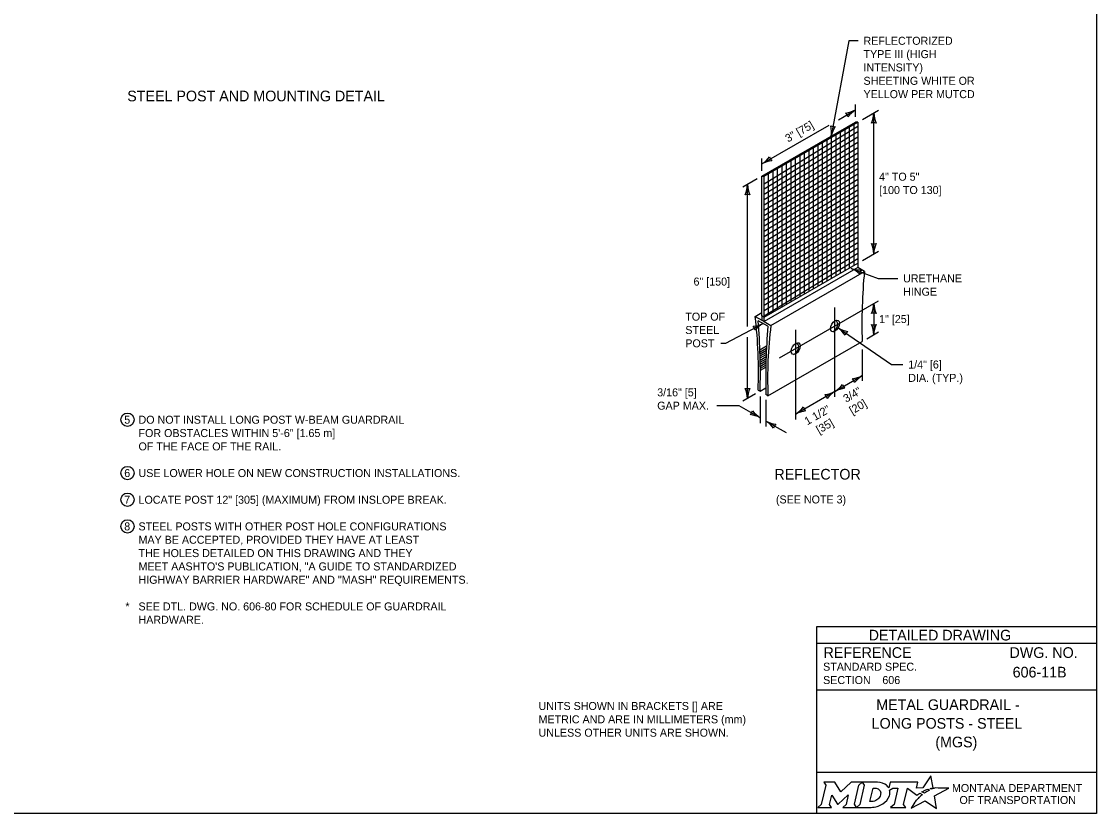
# Model space of a CAD drawing. Extents: x 49991.4 to 50021, y 49987.6 to 50011.4.
# Drawn here: x 50008.69 to 50016.75, y 49987.8 to 49993.74 of the extents above; entities that cross this region are included whole.
import ezdxf

# ---------------------------------------------------------------- set-up
doc = ezdxf.new("R2010")
doc.units = 0
for name, color, linetype in [('Default', 7, 'Continuous'), ('Level 1', 7, 'Continuous'), ('Level 2', 7, 'Continuous'), ('Level 3', 7, 'Continuous'), ('Level 5', 7, 'Continuous')]:
    doc.layers.add(name, color=color, linetype=linetype)

msp = doc.modelspace()

# ---------------------------------------------------------------- linework, layer by layer
at = {"layer": 'Default'}
for points in [[(50015.5126, 49987.9811), (50015.5023, 49987.9867), (50015.5139, 49987.9895), (50015.5255, 49987.9915), (50015.5081, 49988.0816), (50015.4486, 49987.9903), (50015.4013, 49987.9896), (50015.4116, 49988.0337), (50015.2024, 49988.0338), (50015.1923, 49987.9913), (50015.1865, 49987.9996)], [(50014.7056, 49988.0338), (50014.7197, 49988.0104), (50014.6862, 49987.8671), (50014.6605, 49987.8446), (50014.7621, 49987.8446), (50014.7486, 49987.8674), (50014.7648, 49987.9375), (50014.8085, 49987.8685), (50014.8138, 49987.8685), (50014.8889, 49987.938), (50014.8725, 49987.8669), (50014.8478, 49987.8449), (50014.9494, 49987.8449), (50014.9356, 49987.8682), (50014.9688, 49988.0106)], [(50014.9688, 49988.0106), (50014.9941, 49988.0338), (50014.9117, 49988.0338), (50014.8321, 49987.9608), (50014.7876, 49988.0335), (50014.7056, 49988.0338)], [(50015.1077, 49988.0338), (50014.9941, 49988.0338), (50015.0088, 49988.0109), (50014.9749, 49987.8671), (50014.9494, 49987.8449), (50015.06, 49987.8449)], [(50015.1317, 49987.9471), (50015.1305, 49987.939), (50015.1273, 49987.9297), (50015.1231, 49987.9215), (50015.1175, 49987.914), (50015.111, 49987.9071), (50015.1031, 49987.9008), (50015.0948, 49987.8961), (50015.0857, 49987.8922), (50015.0766, 49987.8899), (50015.0674, 49987.889), (50015.0515, 49987.889), (50015.0751, 49987.989), (50015.0911, 49987.989), (50015.0987, 49987.9884), (50015.1063, 49987.9865), (50015.1129, 49987.9835), (50015.119, 49987.9793), (50015.1238, 49987.9743), (50015.1275, 49987.9683), (50015.1302, 49987.9621), (50015.1318, 49987.9547), (50015.1318, 49987.9517), (50015.1317, 49987.9471)], [(50015.1991, 49987.9747), (50015.2237, 49987.9878), (50015.2606, 49987.9878), (50015.232, 49987.8673), (50015.2045, 49987.8446), (50015.3207, 49987.8446), (50015.3037, 49987.8675), (50015.3319, 49987.9877), (50015.4032, 49987.936), (50015.4243, 49987.9511), (50015.444, 49987.9402)], [(50015.3882, 49987.8843), (50015.3729, 49987.8599), (50015.3682, 49987.8524), (50015.3624, 49987.8438), (50015.3601, 49987.8395), (50015.4654, 49987.8926), (50015.5493, 49987.8375), (50015.5362, 49987.9302), (50015.6431, 49987.9886), (50015.5938, 49987.9894), (50015.5637, 49987.9898), (50015.5429, 49987.9901), (50015.5361, 49987.9886), (50015.5312, 49987.9874), (50015.5228, 49987.9851), (50015.5126, 49987.9811)], [(50015.4622, 49987.9535), (50015.4598, 49987.9518), (50015.4415, 49987.9614), (50015.4518, 49987.9671), (50015.4559, 49987.9693), (50015.4645, 49987.9733), (50015.4702, 49987.9759), (50015.4781, 49987.9789), (50015.4854, 49987.9816), (50015.4972, 49987.9742), (50015.4932, 49987.9721), (50015.4886, 49987.9696), (50015.4844, 49987.9674), (50015.4794, 49987.9645), (50015.4775, 49987.9634), (50015.4748, 49987.9618), (50015.4723, 49987.9604), (50015.47, 49987.9588), (50015.4674, 49987.957), (50015.4647, 49987.9552), (50015.4622, 49987.9535)], [(50015.1057, 49987.8522), (50015.1141, 49987.8548), (50015.1271, 49987.8602), (50015.1475, 49987.8712)], [(50015.4021, 49987.9004), (50015.4021, 49987.9004)]]:
    msp.add_lwpolyline(points, dxfattribs=at)
for centre, radius, start, end in [((50015.0868, 49987.9727), 0.1183, 300.91025, 339.13831), ((50015.1308, 49987.9554), 0.0709, 339.53292, 15.85821)]:
    msp.add_arc(centre, radius, start, end, dxfattribs=at)
for centre, major_axis, ratio, start_param, end_param in [((50015.1056, 49987.9864), (0.0834, -0.0037), 0.568097, 0.61298, 1.570796), ((50015.1612, 49987.9937), (0.0361, -0.0295), 0.469099, 1.225588, 1.570796), ((50015.4119, 49987.9106), (-0.0098, -0.0102), 0.016458, 3.141593, 6.279097), ((50015.4329, 49987.9305), (-0.0112, -0.0097), 0.021651, 3.157348, 6.283185), ((50015.0603, 49987.9932), (0, 0.1484), 0.987302, 3.139398, 3.456847), ((50015.3952, 49987.8923), (-0.00694, -0.00806), 0.008222, 0, 3.137361)]:
    msp.add_ellipse(centre, major_axis=major_axis, ratio=ratio, start_param=start_param, end_param=end_param, dxfattribs=at)
at = {"layer": 'Level 1'}
for p, q in [((50014.2414, 49992.5772), (50014.9429, 49992.9822)), ((50014.2583, 49992.5772), (50014.9598, 49992.9822)), ((50014.2583, 49992.5211), (50014.9598, 49992.9514)), ((50014.8651, 49991.8714), (50014.8651, 49992.9276)), ((50014.8988, 49991.8909), (50014.8988, 49992.9471)), ((50014.9326, 49991.9104), (50014.9326, 49992.9665)), ((50014.9598, 49992.9822), (50014.9429, 49992.9822)), ((50014.9598, 49992.9822), (50014.9598, 49991.9261)), ((50014.2583, 49992.4815), (50014.9598, 49992.9118)), ((50014.2583, 49992.4419), (50014.9598, 49992.8722)), ((50014.7301, 49991.7935), (50014.7301, 49992.8496)), ((50014.7638, 49991.813), (50014.7638, 49992.8691)), ((50014.7976, 49991.8325), (50014.7976, 49992.8886)), ((50014.8313, 49991.852), (50014.8313, 49992.9081)), ((50014.2583, 49992.4023), (50014.9598, 49992.8326)), ((50014.2583, 49992.3627), (50014.9598, 49992.793)), ((50014.2583, 49992.3231), (50014.9598, 49992.7534)), ((50014.5951, 49991.7156), (50014.5951, 49992.7717)), ((50014.6288, 49991.735), (50014.6288, 49992.7912)), ((50014.6626, 49991.7545), (50014.6626, 49992.8107)), ((50014.6963, 49991.774), (50014.6963, 49992.8301)), ((50014.2583, 49992.2836), (50014.9598, 49992.7138)), ((50014.2583, 49992.244), (50014.9598, 49992.6742)), ((50014.4263, 49991.6181), (50014.4263, 49992.6743)), ((50014.4601, 49991.6376), (50014.4601, 49992.6937)), ((50014.4938, 49991.6571), (50014.4938, 49992.7132)), ((50014.5276, 49991.6766), (50014.5276, 49992.7327)), ((50014.5613, 49991.6961), (50014.5613, 49992.7522)), ((50014.2583, 49992.2044), (50014.9598, 49992.6346)), ((50014.2583, 49992.1648), (50014.9598, 49992.595)), ((50014.2913, 49991.5402), (50014.2913, 49992.5963)), ((50014.3251, 49991.5597), (50014.3251, 49992.6158)), ((50014.3588, 49991.5792), (50014.3588, 49992.6353)), ((50014.3926, 49991.5986), (50014.3926, 49992.6548)), ((50014.2414, 49991.5309), (50014.2414, 49992.5772)), ((50014.2414, 49992.5772), (50014.2583, 49992.5772)), ((50014.2583, 49991.5211), (50014.2583, 49992.5772)), ((50014.2583, 49992.1252), (50014.9598, 49992.5554)), ((50014.2583, 49992.0856), (50014.9598, 49992.5158)), ((50014.2583, 49992.046), (50014.9598, 49992.4762)), ((50014.2583, 49992.0064), (50014.9598, 49992.4367)), ((50014.2583, 49991.9668), (50014.9598, 49992.3971)), ((50014.2583, 49991.9272), (50014.9598, 49992.3575)), ((50014.2583, 49991.8876), (50014.9598, 49992.3179)), ((50014.2583, 49991.848), (50014.9598, 49992.2783)), ((50014.2583, 49991.8084), (50014.9598, 49992.2387)), ((50014.2583, 49991.7688), (50014.9598, 49992.1991)), ((50014.2583, 49991.7293), (50014.9598, 49992.1595)), ((50014.2583, 49991.6897), (50014.9598, 49992.1199)), ((50014.2583, 49991.6501), (50014.9598, 49992.0803)), ((50014.2583, 49991.6105), (50014.9598, 49992.0407)), ((50014.2583, 49991.5709), (50014.9598, 49992.0011)), ((50014.2583, 49991.5313), (50014.9598, 49991.9615)), ((50014.2583, 49991.5211), (50014.9598, 49991.9261)), ((50014.9598, 49991.8924), (50014.2583, 49991.4874)), ((50014.9598, 49991.9261), (50014.9598, 49991.8924)), ((50014.9598, 49991.9219), (50014.9598, 49991.9219)), ((50015.0099, 49991.8636), (50014.9598, 49991.8924)), ((50014.3084, 49991.4586), (50015.0099, 49991.8636)), ((50014.1915, 49991.5261), (50014.2414, 49991.5549)), ((50014.1915, 49991.5261), (50014.2414, 49991.4972)), ((50014.2865, 49991.4517), (50014.2134, 49991.4939)), ((50014.2583, 49991.5211), (50014.2414, 49991.5309)), ((50014.2414, 49991.5309), (50014.2414, 49991.4972)), ((50014.2414, 49991.4972), (50014.2583, 49991.4874)), ((50014.2583, 49991.4874), (50014.2583, 49991.5211)), ((50014.2583, 49991.4874), (50014.2583, 49991.5211)), ((50014.2583, 49991.4874), (50014.3084, 49991.4586)), ((50014.2264, 49991.2758), (50014.2762, 49991.3045)), ((50014.2865, 49990.9312), (50014.993, 49991.3391)), ((50014.227, 49991.2605), (50014.2754, 49991.2885)), ((50014.2275, 49991.2452), (50014.2746, 49991.2724)), ((50014.2279, 49991.2299), (50014.2739, 49991.2564)), ((50014.2283, 49991.2145), (50014.2733, 49991.2405)), ((50014.2287, 49991.1991), (50014.2727, 49991.2246)), ((50014.229, 49991.1837), (50014.2722, 49991.2087)), ((50014.2292, 49991.1683), (50014.2717, 49991.1928)), ((50014.2295, 49991.1528), (50014.2713, 49991.177)), ((50014.2296, 49991.1373), (50014.2709, 49991.1612)), ((50014.2297, 49991.1218), (50014.2706, 49991.1454)), ((50014.2281, 49990.965), (50014.2707, 49990.9896)), ((50014.2134, 49990.9734), (50014.2281, 49990.965)), ((50014.2865, 49990.9312), (50014.2719, 49990.9396))]:
    msp.add_line(p, q, dxfattribs=at)
msp.add_lwpolyline([(49999.3835, 49998.9992), (50016.7501, 49998.9992), (50016.7501, 49987.7988), (49999.3835, 49987.7988)], close=True, dxfattribs=at)
for centre, radius, start, end in [((50019.1969, 49991.4663), 4.2058, 174.58065, 181.73332), ((50010.5166, 49991.1035), 3.6991, 357.984, 6.55893), ((50009.3581, 49991.0951), 4.8717, 358.46937, 4.69582), ((50018.6911, 49991.0698), 4.4211, 175.04388, 181.68667), ((50017.51, 49991.0613), 3.2261, 172.92757, 182.31169)]:
    msp.add_arc(centre, radius, start, end, dxfattribs=at)
for centre, major_axis in [((50014.7886, 49991.4549), (0.0239, 0.0413)), ((50014.4947, 49991.2852), (0.024, 0.0415))]:
    msp.add_ellipse(centre, major_axis=major_axis, ratio=0.57735, dxfattribs=at)
for centre, major_axis, start_param, end_param in [((50014.778, 49991.4507), (0.0228, 0.0395), 3.80014, 6.895622), ((50014.487, 49991.2803), (0.0214, 0.0371), 3.593264, 7.511454)]:
    msp.add_ellipse(centre, major_axis=major_axis, ratio=0.57735, start_param=start_param, end_param=end_param, dxfattribs=at)
at = {"layer": 'Level 2'}
for centre in [(50009.4843, 49990.7517), (50009.4843, 49990.3517), (50009.4843, 49990.1517), (50009.4843, 49989.9517)]:
    msp.add_circle(centre, 0.05, dxfattribs=at)
at = {"layer": 'Level 3'}
for p, q in [((50014.894, 49993.5927), (50014.761, 49992.8772)), ((50014.9631, 49993.5927), (50014.894, 49993.5927)), ((50014.9429, 49993.0222), (50014.9429, 49993.1146)), ((50014.8148, 49993.0007), (50014.9429, 49993.0746)), ((50014.9944, 49993.0022), (50015.1147, 49993.0717)), ((50015.0801, 49991.9956), (50015.0801, 49993.0517)), ((50014.2414, 49992.6696), (50014.7456, 49992.9607)), ((50014.2414, 49992.6172), (50014.2414, 49992.7096)), ((50014.2068, 49992.5572), (50014.0988, 49992.4949)), ((50014.1334, 49991.4506), (50014.1334, 49992.5149)), ((50014.9944, 49991.9461), (50015.1147, 49992.0156)), ((50014.91, 49991.8858), (50015.1133, 49991.8113)), ((50015.1133, 49991.8113), (50015.2601, 49991.8113)), ((50015.0801, 49991.6232), (50015.0801, 49991.3894)), ((50013.972, 49991.3243), (50014.25, 49991.4728)), ((50014.8125, 49991.4412), (50015.214, 49991.1654)), ((50015.0277, 49991.3591), (50015.1147, 49991.4094)), ((50013.9331, 49991.3243), (50013.972, 49991.3243)), ((50014.1334, 49990.9103), (50014.1334, 49991.3706)), ((50014.993, 49991.2772), (50014.993, 49991.0419)), ((50015.214, 49991.1654), (50015.2986, 49991.1654)), ((50014.7886, 49990.9639), (50014.993, 49991.0819)), ((50014.1934, 49990.945), (50014.0988, 49990.8903)), ((50014.2281, 49990.925), (50014.2281, 49990.7264)), ((50014.2719, 49990.8996), (50014.2719, 49990.7011)), ((50014.7886, 49990.9639), (50014.4947, 49990.7942)), ((50014.0718, 49990.8566), (50013.9035, 49990.8566)), ((50014.2281, 49990.7664), (50014.0718, 49990.8566)), ((50014.2719, 49990.7411), (50014.4221, 49990.6544))]:
    msp.add_line(p, q, dxfattribs=at)
for centre, radius, start, end in [((50014.8398, 49993.2716), 0.2223, 277.45601, 297.63952), ((50014.8319, 49993.0105), 0.0548, 12.13882, 47.86118), ((50015.0692, 49992.8788), 0.233, 122.82731, 142.07716), ((50014.8579, 49993.0608), 0.2223, 337.45601, 357.63952), ((50015.3128, 49993.0632), 0.233, 182.82731, 202.07716), ((50014.7844, 49993.0033), 0.0548, 241.60423, 277.32659), ((50014.5301, 49992.9084), 0.233, 352.29272, 11.54257), ((50014.9777, 49992.8276), 0.2223, 146.92142, 167.10493), ((50015.0801, 49992.9235), 0.0548, 72.13882, 107.86118), ((50014.1151, 49992.8654), 0.233, 302.82731, 322.07716), ((50014.3446, 49992.4727), 0.2223, 97.45601, 117.63952), ((50014.3525, 49992.7337), 0.0548, 192.13882, 227.86118), ((50013.9113, 49992.5241), 0.2223, 337.45601, 357.63952), ((50014.3662, 49992.5264), 0.233, 182.82731, 202.07716), ((50014.1334, 49992.3867), 0.0548, 72.13882, 107.86118), ((50015.0801, 49992.1238), 0.0548, 252.13882, 287.86118), ((50014.8473, 49991.9841), 0.233, 2.82731, 22.07716), ((50015.3022, 49991.9864), 0.2223, 157.45601, 177.63952), ((50014.8249, 49991.6804), 0.2223, 47.31042, 67.49393), ((50014.9794, 49992.1083), 0.233, 252.68172, 271.93157), ((50015.0304, 49991.8417), 0.0548, 141.99323, 177.71559), ((50014.8579, 49991.6323), 0.2223, 337.45601, 357.63952), ((50015.0801, 49991.495), 0.0548, 72.13882, 107.86118), ((50015.3128, 49991.6347), 0.233, 182.82731, 202.07716), ((50014.1534, 49991.6731), 0.2223, 275.56316, 295.74667), ((50014.3697, 49991.273), 0.233, 120.93446, 140.18431), ((50015.0801, 49991.5176), 0.0548, 252.13882, 287.86118), ((50014.8473, 49991.3779), 0.233, 2.82731, 22.07716), ((50015.3022, 49991.3802), 0.2223, 157.45601, 177.63952), ((50014.1369, 49991.4124), 0.0548, 10.24597, 45.96833), ((50014.6792, 49991.2632), 0.2223, 32.97928, 53.16279), ((50014.9348, 49991.6395), 0.233, 238.35058, 257.60043), ((50014.9182, 49991.3686), 0.0548, 127.66209, 163.38445), ((50014.8899, 49991.2789), 0.2223, 277.45601, 297.63952), ((50015.1193, 49990.8861), 0.233, 122.82731, 142.07716), ((50014.1334, 49991.0385), 0.0548, 252.13882, 287.86118), ((50013.9007, 49990.8988), 0.233, 2.82731, 22.07716), ((50014.3556, 49990.9012), 0.2223, 157.45601, 177.63952), ((50014.6623, 49991.1597), 0.233, 302.82731, 322.07716), ((50014.8918, 49990.7669), 0.2223, 97.45601, 117.63952), ((50014.8997, 49991.028), 0.0548, 192.13882, 227.86118), ((50014.882, 49991.0178), 0.0548, 12.13882, 47.86118), ((50014.6855, 49991.1608), 0.2223, 277.45601, 297.63952), ((50014.6776, 49990.8998), 0.0548, 12.13882, 47.86118), ((50014.9149, 49990.7681), 0.233, 122.82731, 142.07716), ((50014.117, 49990.8305), 0.0548, 312.13882, 347.86118), ((50014.3471, 49990.9542), 0.2223, 217.45601, 237.63952), ((50014.3684, 49990.99), 0.233, 302.82731, 322.07716), ((50014.6057, 49990.8583), 0.0548, 192.13882, 227.86118), ((50014.1217, 49990.5591), 0.233, 62.82731, 82.07716), ((50014.1529, 49990.5533), 0.2223, 37.45601, 57.63952), ((50014.3783, 49990.9484), 0.233, 242.82731, 262.07716), ((50014.5978, 49990.5972), 0.2223, 97.45601, 117.63952), ((50014.3829, 49990.677), 0.0548, 132.13882, 167.86118)]:
    msp.add_arc(centre, radius, start, end, dxfattribs=at)
at = {"layer": 'Level 5'}
for p, q in [((50014.3742, 49991.2156), (50015.1147, 49991.6432)), ((50014.7886, 49990.9239), (50014.7886, 49991.5939)), ((50014.4947, 49990.7542), (50014.4947, 49991.4244)), ((50016.7501, 49989.1988), (50014.6501, 49989.1988)), ((50014.6501, 49989.1988), (50014.6501, 49987.7988)), ((50016.7501, 49989.0738), (50014.6501, 49989.0738)), ((50016.3862, 49988.8587), (50016.3862, 49988.8587)), ((50016.7501, 49988.7238), (50014.6501, 49988.7238)), ((50015.1444, 49988.7993), (50015.1444, 49988.7993)), ((50015.7001, 49988.4747), (50015.7001, 49988.4747)), ((50016.7501, 49988.1057), (50014.6501, 49988.1057))]:
    msp.add_line(p, q, dxfattribs=at)

# ---------------------------------------------------------------- texts
at = {"layer": 'Default'}
for s, p in [('MONTANA DEPARTMENT', (50015.6663, 49987.96)), ('OF TRANSPORTATION', (50015.7225, 49987.87))]:
    msp.add_text(s, height=0.06, dxfattribs=at).set_placement(p)
at = {"layer": 'Level 2'}
for s, height, p in [('REFLECTORIZED', 0.06, (50015.0031, 49993.5627)), ('TYPE III (HIGH', 0.06, (50015.0031, 49993.4627)), ('INTENSITY)', 0.06, (50015.0031, 49993.3627)), ('SHEETING WHITE OR', 0.06, (50015.0031, 49993.2627)), ('STEEL POST AND MOUNTING DETAIL', 0.08, (50009.4826, 49993.1388)), ('YELLOW PER MUTCD', 0.06, (50015.0031, 49993.1627)), ('4" TO 5" ', 0.06, (50015.1201, 49992.5436)), ('[100 TO 130]', 0.06, (50015.1201, 49992.4436)), ('6" [150]', 0.06, (50013.7285, 49991.7572)), ('URETHANE', 0.06, (50015.3001, 49991.7813)), ('HINGE', 0.06, (50015.3001, 49991.6813)), ('TOP OF', 0.06, (50013.6669, 49991.4943)), ('1" [25]', 0.06, (50015.1201, 49991.4763)), ('STEEL', 0.06, (50013.6669, 49991.3943)), ('POST', 0.06, (50013.6669, 49991.2943)), ('1/4" [6]', 0.06, (50015.3386, 49991.1354)), ('DIA. (TYP.)', 0.06, (50015.3386, 49991.0354)), ('3/16" [5]', 0.06, (50013.4562, 49990.9266)), ('GAP MAX.', 0.06, (50013.4562, 49990.8266)), ('5', 0.06, (50009.46, 49990.7214)), ('DO NOT INSTALL LONG POST W-BEAM GUARDRAIL ', 0.06, (50009.567, 49990.7214)), ('FOR OBSTACLES WITHIN 5\'-6" [1.65 m]  ', 0.06, (50009.567, 49990.6214)), ('OF THE FACE OF THE RAIL.', 0.06, (50009.567, 49990.5214)), ('6', 0.06, (50009.46, 49990.3214)), ('USE LOWER HOLE ON NEW CONSTRUCTION INSTALLATIONS.', 0.06, (50009.567, 49990.3214)), ('REFLECTOR', 0.08, (50014.3347, 49990.3026)), ('7', 0.06, (50009.46, 49990.1214)), ('LOCATE POST 12" [305] (MAXIMUM) FROM INSLOPE BREAK.', 0.06, (50009.567, 49990.1214)), ('(SEE NOTE 3)', 0.06, (50014.3465, 49990.1237)), ('8', 0.06, (50009.46, 49989.9214)), ('STEEL POSTS WITH OTHER POST HOLE CONFIGURATIONS ', 0.06, (50009.567, 49989.9214)), ('MAY BE ACCEPTED, PROVIDED THEY HAVE AT LEAST ', 0.06, (50009.567, 49989.8214)), ('THE HOLES DETAILED ON THIS DRAWING AND THEY ', 0.06, (50009.567, 49989.7214)), ('MEET AASHTO\'S PUBLICATION, "A GUIDE TO STANDARDIZED', 0.06, (50009.567, 49989.6214)), ('HIGHWAY BARRIER HARDWARE" AND "MASH" REQUIREMENTS.', 0.06, (50009.567, 49989.5214)), ('*', 0.06, (50009.4684, 49989.3214)), ('SEE DTL. DWG. NO. 606-80 FOR SCHEDULE OF GUARDRAIL ', 0.06, (50009.567, 49989.3214)), ('HARDWARE.', 0.06, (50009.567, 49989.2214)), ('606-11B', 0.08, (50016.1214, 49988.8187)), ('606', 0.06, (50015.1444, 49988.7693)), ('METAL GUARDRAIL -', 0.08, (50015.0988, 49988.5747)), ('UNITS SHOWN IN BRACKETS [] ARE', 0.06, (50012.5665, 49988.5749)), ('METRIC AND ARE IN MILLIMETERS (mm)', 0.06, (50012.5665, 49988.4749)), (' LONG POSTS - STEEL', 0.08, (50015.0344, 49988.4347)), ('UNLESS OTHER UNITS ARE SHOWN.', 0.06, (50012.5665, 49988.3749)), ('(MGS)', 0.08, (50015.5417, 49988.2947))]:
    msp.add_text(s, height=height, dxfattribs=at).set_placement(p)
for s, p in [('3" [75]', (50014.4375, 49992.829)), (' 3/4"', (50014.8536, 49990.8671)), ('[20]', (50014.9182, 49990.7889)), ('1 1/2"', (50014.5817, 49990.7088)), ('[35]', (50014.6696, 49990.6441))]:
    msp.add_text(s, height=0.06, rotation=30, dxfattribs=at).set_placement(p)
at = {"layer": 'Level 5'}
for s, height, p in [('DETAILED DRAWING', 0.0799, (50015.0418, 49989.0963)), ('REFERENCE', 0.08, (50014.7037, 49988.9654)), ('DWG. NO.', 0.08, (50016.0979, 49988.9654)), ('STANDARD SPEC.', 0.06, (50014.7004, 49988.8694)), ('SECTION', 0.06, (50014.7004, 49988.7694))]:
    msp.add_text(s, height=height, dxfattribs=at).set_placement(p)

doc.saveas('drawing.dxf')
